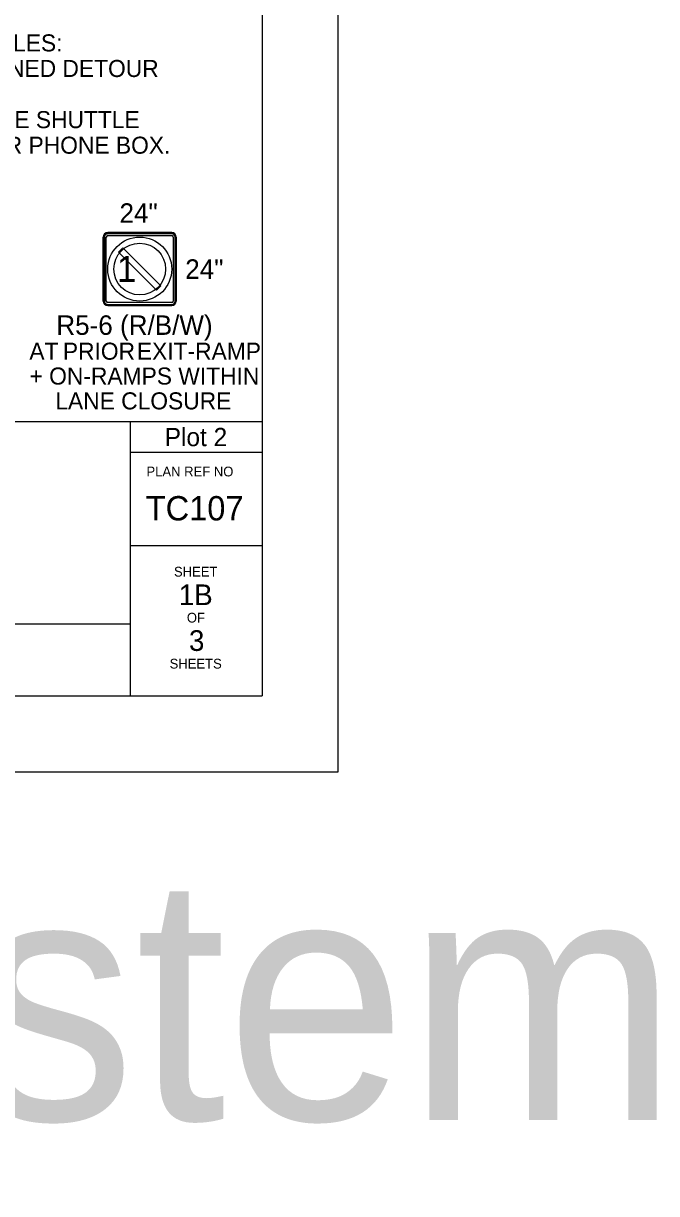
# Model space of a CAD drawing. Extents: x 99999 to 100116, y 99995 to 100013.
# Drawn here: x 100034.769 to 100037.37, y 99997.956 to 100002.761 of the extents above; entities that cross this region are included whole.
import ezdxf

# ---------------------------------------------------------------- set-up
doc = ezdxf.new("R2010")
doc.units = 0
for name, color, linetype in [('SH_GI_GeneralNotesBodyText', 7, 'Continuous'), ('SH_GI_PlotLimits', 7, 'Continuous'), ('SH_GI_SheetBorder', 7, 'Continuous'), ('SH_GI_SheetLocationText', 7, 'Continuous'), ('SH_GI_SheetTextInCells', 7, 'Continuous'), ('SH_GI_TitleBlockText', 7, 'Continuous'), ('TR_SN_ConstructionSigns', 7, 'Continuous')]:
    doc.layers.add(name, color=color, linetype=linetype)

msp = doc.modelspace()

# ---------------------------------------------------------------- linework, layer by layer
at = {"layer": 'SH_GI_PlotLimits'}
msp.add_lwpolyline([(100019.0625, 99999.6875), (100036.0625, 99999.6875), (100036.0625, 100010.6875), (100019.0625, 100010.6875)], close=True, dxfattribs=at)
at = {"layer": 'SH_GI_SheetBorder'}
for p, q in [((100035.75, 100010.375), (100035.75, 100000)), ((100020, 100001.1259), (100035.75, 100001.1259)), ((100035.2079, 100001.1259), (100035.2079, 100000)), ((100035.2079, 100001.0008), (100035.75, 100001.0008)), ((100035.2079, 100000.6176), (100035.75, 100000.6176)), ((100032.2055, 100000.2955), (100035.2079, 100000.2955)), ((100020, 100000), (100035.75, 100000))]:
    msp.add_line(p, q, dxfattribs=at)
at = {"layer": 'TR_SN_ConstructionSigns'}
for p, q in [((100035.0971, 100001.8831), (100035.0971, 100001.6206)), ((100035.0971, 100001.6206), (100035.0971, 100001.8831)), ((100035.0971, 100001.8831), (100035.0971, 100001.6206)), ((100035.1018, 100001.8831), (100035.1018, 100001.6206)), ((100035.1096, 100001.6206), (100035.1096, 100001.8831)), ((100035.3783, 100001.9019), (100035.1158, 100001.9019)), ((100035.1158, 100001.9019), (100035.3783, 100001.9019)), ((100035.3783, 100001.9019), (100035.1158, 100001.9019)), ((100035.3783, 100001.8972), (100035.1158, 100001.8972)), ((100035.1158, 100001.8894), (100035.3783, 100001.8894)), ((100035.3846, 100001.8831), (100035.3846, 100001.6206)), ((100035.3924, 100001.6206), (100035.3924, 100001.8831)), ((100035.3971, 100001.6206), (100035.3971, 100001.8831)), ((100035.3971, 100001.8831), (100035.3971, 100001.6206)), ((100035.3971, 100001.6206), (100035.3971, 100001.8831)), ((100035.3783, 100001.6144), (100035.1158, 100001.6144)), ((100035.1158, 100001.6066), (100035.3783, 100001.6066)), ((100035.1158, 100001.6019), (100035.3783, 100001.6019)), ((100035.3783, 100001.6019), (100035.1158, 100001.6019)), ((100035.1158, 100001.6019), (100035.3783, 100001.6019))]:
    msp.add_line(p, q, dxfattribs=at)
msp.add_lwpolyline([(100035.3305, 100001.6861), (100035.1813, 100001.8353), (100035.1778, 100001.8389), (100035.1601, 100001.8212), (100035.3128, 100001.6685), (100035.3164, 100001.6649), (100035.3341, 100001.6826), (100035.3305, 100001.6861)], dxfattribs=at)
for radius in [0.1313, 0.1062]:
    msp.add_circle((100035.2471, 100001.7519), radius, dxfattribs=at)
for centre, radius, start, end in [((100035.1158, 100001.8831), 0.0187, 90, 180), ((100035.1158, 100001.8831), 0.0187, 90, 180), ((100035.1158, 100001.8831), 0.0187, 90, 180), ((100035.1158, 100001.8831), 0.0141, 90, 180), ((100035.1158, 100001.8831), 0.00625, 90, 180), ((100035.3783, 100001.8831), 0.0187, 0, 90), ((100035.3783, 100001.8831), 0.0187, 0, 90), ((100035.3783, 100001.8831), 0.0187, 0, 90), ((100035.3783, 100001.8831), 0.0141, 0, 90), ((100035.3783, 100001.8831), 0.00625, 0, 90), ((100035.1158, 100001.6206), 0.0187, 180, 270), ((100035.1158, 100001.6206), 0.0187, 180, 270), ((100035.1158, 100001.6206), 0.0187, 180, 270), ((100035.1158, 100001.6206), 0.0141, 180, 270), ((100035.1158, 100001.6206), 0.00625, 180, 270), ((100035.3783, 100001.6206), 0.0141, 270, 0), ((100035.3783, 100001.6206), 0.00625, 270, 0), ((100035.3783, 100001.6206), 0.0187, 270, 0), ((100035.3783, 100001.6206), 0.0187, 270, 0), ((100035.3783, 100001.6206), 0.0187, 270, 0)]:
    msp.add_arc(centre, radius, start, end, dxfattribs=at)

# ---------------------------------------------------------------- texts
at = {"layer": 'SH_GI_GeneralNotesBodyText'}
for s, p in [('11. BICYCLIST ACCOMMODATIONS, WHERE FACILITY OPEN TO BICYCLES:', (100031.549, 100002.6456)), ('(A) BICYCLES PROHIBITED VIA R5-601 & R5-6 SIGNS. PROVIDE SIGNED DETOUR ', (100031.689, 100002.5406)), ('(B) BICYCLES PROHIBITED VIA R5-601 & R5-6 SIGNS. PROVIDE FREE SHUTTLE ', (100031.689, 100002.3306)), ('(WORK TRUCK, VAN, OR BUS OK) + CONTACT INFORMATION OR PHONE BOX.', (100031.839, 100002.2256))]:
    msp.add_text(s, height=0.07, rotation=360, dxfattribs=at).set_placement(p)
at = {"layer": 'SH_GI_SheetBorder'}
msp.add_text('PLAN REF NO', height=0.040032, dxfattribs=at).set_placement((100035.2747, 100000.9008))
at = {"layer": 'SH_GI_SheetLocationText'}
for s, height, p in [('Plot 2', 0.075, (100035.3497, 100001.025)), ('3-Mile Queue Warning System', 1, (100019.2499, 99998.258))]:
    msp.add_text(s, height=height, dxfattribs=at).set_placement(p)
at = {"layer": 'SH_GI_SheetTextInCells'}
for s, p in [('SHEET', (100035.3877, 100000.4896)), ('OF', (100035.4406, 100000.3008)), ('SHEETS', (100035.3698, 100000.112))]:
    msp.add_text(s, height=0.04003, dxfattribs=at).set_placement(p)
at = {"layer": 'SH_GI_TitleBlockText'}
for s, height, p in [('TC107', 0.1, (100035.2718, 100000.72)), ('1B', 0.085, (100035.4076, 100000.3723)), ('3', 0.085, (100035.4493, 100000.1843))]:
    msp.add_text(s, height=height, dxfattribs=at).set_placement(p)
at = {"layer": 'TR_SN_ConstructionSigns'}
for s, height, p in [('24"', 0.08, (100035.164, 100001.9419)), ('24"', 0.08, (100035.434, 100001.7119)), ('R5-6 (R/B/W)', 0.08, (100034.9045, 100001.4819)), ('AT', 0.07, (100034.7937, 100001.3799)), ('PRIOR', 0.07, (100034.9314, 100001.3799)), ('EXIT-RAMP', 0.07, (100035.2353, 100001.3799)), ('+ ON-RAMPS WITHIN', 0.07, (100034.7944, 100001.2779)), ('LANE CLOSURE', 0.07, (100034.9003, 100001.1759))]:
    msp.add_text(s, height=height, rotation=360, dxfattribs=at).set_placement(p)
msp.add_text('1', height=0.1065, dxfattribs=at).set_placement((100035.1538, 100001.6994))

doc.saveas('drawing.dxf')
